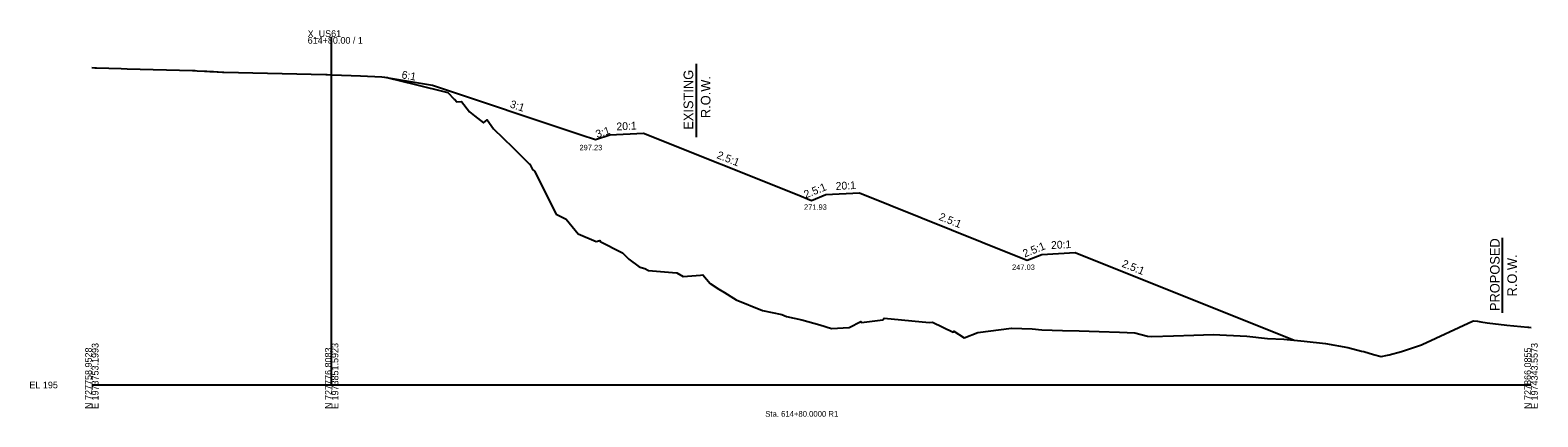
# Model space of a CAD drawing. Extents: x -26 to 1604, y -13 to 9623.
# Drawn here: x -26 to 603, y 6987 to 7148 of the extents above; entities that cross this region are included whole.
import ezdxf

# ---------------------------------------------------------------- set-up
doc = ezdxf.new("R2010")
doc.units = 0
for name, color, linetype in [('Draft_XS_Grid', 7, 'Continuous'), ('Draft_XS_Text', 7, 'Continuous'), ('DTM_X_GROUND', 7, 'Continuous'), ('SLOPE_STAKES_FILL', 7, 'Continuous'), ('XS_CELL', 7, 'Continuous'), ('XS_P_GROUND', 7, 'Continuous'), ('XS_P_ROW', 7, 'Continuous'), ('XS_P_TX_DCH', 7, 'Continuous'), ('XS_P_TX_FS_BS', 7, 'Continuous'), ('XS_X_ROW', 7, 'Continuous')]:
    doc.layers.add(name, color=color, linetype=linetype)

msp = doc.modelspace()

# ---------------------------------------------------------------- linework, layer by layer
at = {"layer": 'DTM_X_GROUND'}
msp.add_lwpolyline([(0, 7132.22), (1.29, 7132.19), (1.55, 7132.18), (1.81, 7132.18), (1.98, 7132.17), (12.31, 7131.93), (14.81, 7131.77), (42.04, 7131.01), (42.62, 7130.99), (43.04, 7130.97), (43.92, 7130.93), (47.02, 7130.8), (47.95, 7130.76), (49.16, 7130.67), (49.95, 7130.61), (50.79, 7130.57), (52.33, 7130.46), (52.75, 7130.44), (54.45, 7130.33), (55.08, 7130.29), (97.57, 7129.35), (97.76, 7129.34), (97.88, 7129.34), (98.11, 7129.33), (100.2, 7129.28), (112.09, 7128.75), (120.94, 7128.35), (123.39, 7128.07), (123.62, 7128.04), (134.4, 7125.35), (148.47, 7121.82), (151.02, 7119.04), (151.4, 7118.9), (152.12, 7118.02), (154.12, 7118.06), (157.45, 7113.84), (159.58, 7112.18), (163.34, 7109.17), (164.84, 7110.44), (167.41, 7106.78), (171.56, 7102.79), (175.59, 7099), (182.39, 7092.17), (182.44, 7092.12), (182.59, 7092.01), (183.73, 7089.8), (184.63, 7089.1), (193.53, 7071.2), (197.75, 7069.08), (202.76, 7063.04), (210.26, 7059.76), (211.74, 7060.25), (211.95, 7059.77), (221.03, 7055.21), (221.25, 7055.1), (223.82, 7052.47), (228.18, 7049.17), (229, 7048.93), (230.52, 7048.55), (232.04, 7047.66), (242.14, 7046.85), (243.87, 7046.71), (246.58, 7045.23), (253.77, 7045.75), (254.68, 7045.82), (257.76, 7042.24), (261.41, 7039.93), (263.7, 7038.49), (267.53, 7036.17), (268.6, 7035.53), (279.58, 7031.02), (287.68, 7029.35), (289.58, 7028.49), (296.07, 7027.11), (303.49, 7024.99), (308.37, 7023.59), (315.71, 7024), (320.54, 7026.41), (320.91, 7025.99), (329.74, 7027.14), (330.34, 7027.8), (349.14, 7026.06), (350.51, 7026.2), (359.04, 7021.96), (359.43, 7022.43), (363.65, 7019.67), (369.41, 7021.85), (383.47, 7023.67), (392, 7023.44), (396.04, 7022.98), (404.61, 7022.73), (411.58, 7022.53), (420.02, 7022.24), (428.49, 7021.95), (434.84, 7021.73), (440.17, 7020.39), (441.86, 7020.2), (450.94, 7020.48), (459.48, 7020.74), (467.52, 7020.99), (481.5, 7020.3), (490.12, 7019.39), (496.93, 7019.14), (505.45, 7018.19), (514.29, 7017.21), (523.58, 7015.54), (529.26, 7014.03), (530.29, 7013.9), (534.31, 7012.75), (537.57, 7011.82), (540.16, 7012.43), (540.81, 7012.62), (545.96, 7013.9), (554.33, 7016.7), (554.61, 7016.8), (575.55, 7026.58), (576.17, 7026.77), (577.71, 7026.55), (579.04, 7026.28), (581.65, 7025.88), (589.92, 7024.95), (598.63, 7024.13), (598.93, 7024.09), (599.14, 7024.07), (600, 7023.95)], dxfattribs=at)
at = {"layer": 'XS_CELL'}
for p, q in [((100, 7000), (100, 7145)), ((0, 7000), (100, 7000)), ((100, 7000), (600, 7000))]:
    msp.add_line(p, q, dxfattribs=at)
at = {"layer": 'XS_P_GROUND'}
for points in [[(122, 7128.23), (142, 7124.9)], [(142, 7124.9), (204, 7104.23), (210, 7102.23), (216, 7104.23), (230, 7104.93), (294, 7079.33), (300, 7076.93), (306, 7079.33), (320, 7080.03), (384, 7054.43), (390, 7052.03), (396, 7054.43), (410, 7055.13), (501.2, 7018.65)]]:
    msp.add_lwpolyline(points, dxfattribs=at)
at = {"layer": 'XS_P_ROW'}
msp.add_line((588, 7061.27), (588, 7030), dxfattribs=at)
at = {"layer": 'XS_X_ROW'}
msp.add_line((252, 7133.84), (252, 7103.29), dxfattribs=at)

# ---------------------------------------------------------------- texts
at = {"layer": 'Draft_XS_Grid'}
msp.add_text('-', height=0.0001, dxfattribs=at).set_placement((0, 7000))
at = {"layer": 'Draft_XS_Text'}
msp.add_text('Sta. 614+80.0000 R1', height=2.4, dxfattribs=at).set_placement((280.75, 6986.75))
at = {"layer": 'SLOPE_STAKES_FILL'}
for p in [(141.96, 7124.84), (203.96, 7104.17), (215.96, 7104.17), (229.96, 7104.87), (209.96, 7102.17), (293.96, 7079.27), (305.96, 7079.27), (319.96, 7079.97), (299.96, 7076.87), (383.96, 7054.37), (395.96, 7054.37), (409.96, 7055.07), (389.96, 7051.97)]:
    msp.add_text('X', height=0.12, dxfattribs=at).set_placement(p)
at = {"layer": 'XS_CELL'}
for s, p in [('X_US61', (90, 7145)), ('614+80.00 / 1', (90, 7142.2)), ('EL 195', (-26, 6998.6))]:
    msp.add_text(s, height=2.8, dxfattribs=at).set_placement(p)
for s, p in [('N 727758.9528', (0, 6990)), ('E 1973753.1993', (2.8, 6990)), ('N 727776.8083', (100, 6990)), ('E 1973851.5923', (102.8, 6990)), ('N 727866.0855', (600, 6990)), ('E 1974343.5573', (602.8, 6990))]:
    msp.add_text(s, height=2.8, rotation=90, dxfattribs=at).set_placement(p)
at = {"layer": 'XS_P_GROUND'}
for p in [(121.96, 7128.17), (501.16, 7018.59)]:
    msp.add_text('X', height=0.12, dxfattribs=at).set_placement(p)
at = {"layer": 'XS_P_ROW'}
for s, p in [('PROPOSED', (586.91, 7030.8)), ('R.O.W.', (594.11, 7036.87))]:
    msp.add_text(s, height=4, rotation=90, dxfattribs=at).set_placement(p)
at = {"layer": 'XS_P_TX_DCH'}
for s, p in [('297.23', (203.32, 7097.81)), ('271.93', (296.91, 7072.99)), ('247.03', (383.65, 7047.93))]:
    msp.add_text(s, height=2.25, dxfattribs=at).set_placement(p)
at = {"layer": 'XS_P_TX_FS_BS'}
for s, rotation, p in [('6:1', 350.53766, (128.99, 7127.8)), ('3:1', 341.56507, (174.07, 7115.73)), ('20:1', 2.86241, (218.79, 7106.06)), ('3:1', 18.43493, (210.69, 7102.84)), ('2.5:1', 338.19859, (260.28, 7094.6)), ('2.5:1', 21.80141, (297.64, 7077.71)), ('20:1', 2.86241, (310.19, 7081.25)), ('2.5:1', 338.19859, (352.83, 7068.9)), ('2.5:1', 21.80141, (388.88, 7053.09)), ('20:1', 2.86241, (399.98, 7056.65)), ('2.5:1', 338.19859, (429.13, 7049.35))]:
    msp.add_text(s, height=3.24, rotation=rotation, dxfattribs=at).set_placement(p)
at = {"layer": 'XS_X_ROW'}
for s, p in [('EXISTING', (250.71, 7106.35)), ('R.O.W.', (257.91, 7111.19))]:
    msp.add_text(s, height=4, rotation=90, dxfattribs=at).set_placement(p)

doc.saveas('drawing.dxf')
